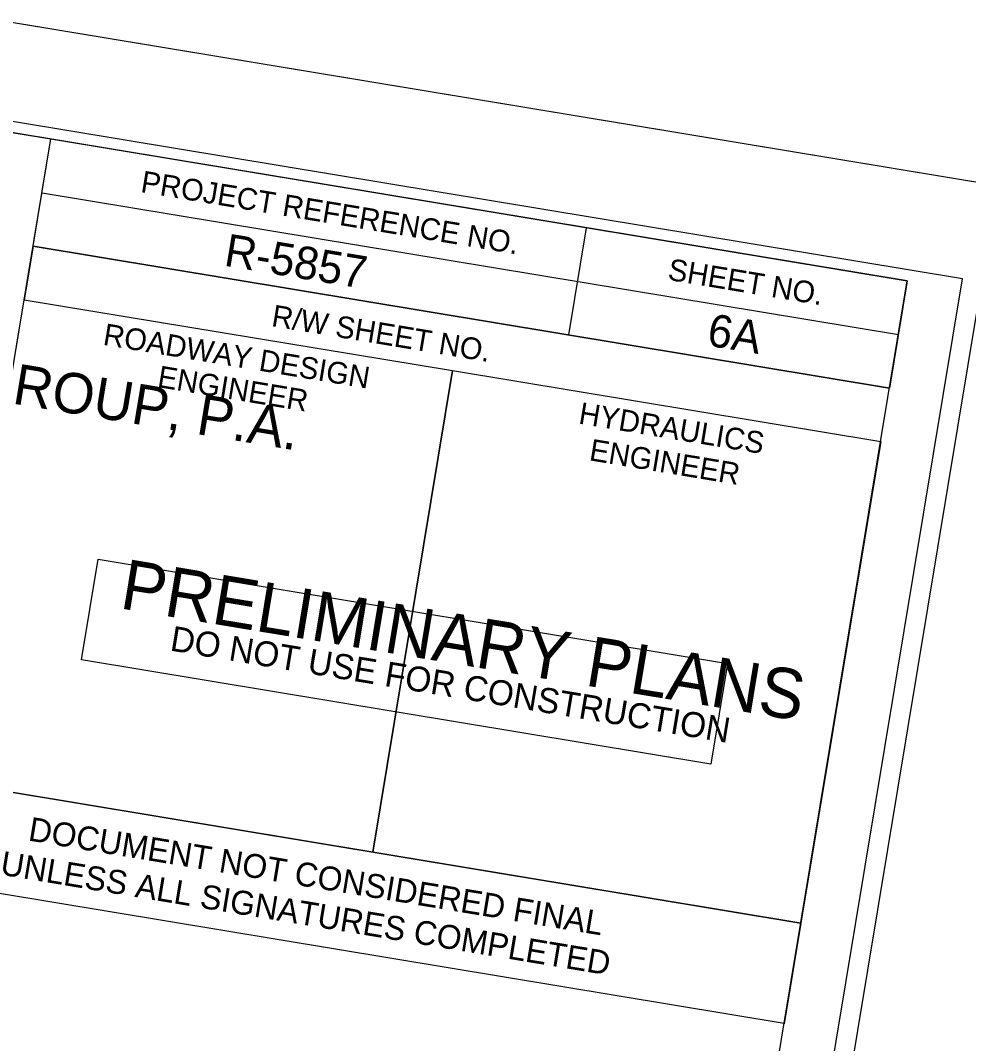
# Model space of a CAD drawing. Extents: x 2191153 to 2193185, y 85349 to 86740.
# Drawn here: x 2192768.6 to 2192987.1, y 86266.7 to 86502.5 of the extents above; entities that cross this region are included whole.
import ezdxf

# ---------------------------------------------------------------- set-up
doc = ezdxf.new("R2010")
doc.units = 0
for name, color, linetype in [('CTL Primary Horizontal CELL', 7, 'Continuous'), ('CTL Primary Horizontal Cogo Comment', 7, 'Continuous'), ('CTL Primary Horizontal Cogo Elevation', 7, 'Continuous'), ('CTL Primary Horizontal Cogo Number', 7, 'Continuous'), ('Exist Other Culture Sign', 7, 'Continuous'), ('Exist Property Iron Pin CELL', 7, 'Continuous'), ('Exist Roads EOP Other', 7, 'Continuous'), ('Exist Structure Minor Storm Sewer Manhole CELL', 7, 'Continuous')]:
    doc.layers.add(name, color=color, linetype=linetype)

msp = doc.modelspace()

# ---------------------------------------------------------------- linework, layer by layer
at = {"layer": 'CTL Primary Horizontal Cogo Comment'}
msp.add_line((2192993.8, 86464.39), (2191332.46, 86739.67), dxfattribs=at)
at = {"layer": 'CTL Primary Horizontal Cogo Elevation'}
msp.add_lwpolyline([(2192993.8, 86464.39), (2191332.46, 86739.67), (2191152.64, 85654.47), (2192813.99, 85379.19)], close=True, dxfattribs=at)
at = {"layer": 'CTL Primary Horizontal Cogo Number'}
msp.add_lwpolyline([(2192985.69, 86442.98), (2191341.61, 86715.4), (2191169.13, 85674.49), (2192813.22, 85402.07)], close=True, dxfattribs=at)
at = {"layer": 'Exist Other Culture Sign'}
for p, q in [((2192773.53, 86462.83), (2192970.89, 86430.13)), ((2192898.95, 86454.72), (2192894.86, 86430.05)), ((2192771.49, 86450.5), (2192769.45, 86438.16)), ((2192771.49, 86450.5), (2192968.85, 86417.79)), ((2192771.49, 86450.5), (2192968.85, 86417.79)), ((2192868.15, 86421.81), (2192849.77, 86310.87))]:
    msp.add_line(p, q, dxfattribs=at)
for points in [[(2192972.95, 86442.51), (2191493.12, 86687.71), (2191321.48, 85651.84), (2192801.3, 85406.63)], [(2192775.59, 86475.21), (2192972.95, 86442.51), (2192968.85, 86417.79), (2192771.49, 86450.5)], [(2192769.45, 86438.16), (2192868.15, 86421.81), (2192849.76, 86310.82), (2192751.06, 86327.18)], [(2192868.15, 86421.81), (2192966.81, 86405.46), (2192948.42, 86294.48), (2192849.76, 86310.82)]]:
    msp.add_lwpolyline(points, close=True, dxfattribs=at)
at = {"layer": 'Exist Property Iron Pin CELL'}
for p in [(2192642.99, 86497.18), (2192767.67, 86427.43)]:
    msp.add_line(p, (2192775.59, 86475.21), dxfattribs=at)
at = {"layer": 'Exist Roads EOP Other'}
msp.add_lwpolyline([(2192782.6, 86355.15), (2192786.45, 86378.33), (2192931.47, 86354.3), (2192927.63, 86331.12)], close=True, dxfattribs=at)
at = {"layer": 'Exist Structure Minor Storm Sewer Manhole CELL'}
for p, q in [((2192751.06, 86327.18), (2192948.4, 86294.48)), ((2192944.56, 86271.29), (2192747.22, 86303.99)), ((2192948.4, 86294.47), (2192944.56, 86271.28))]:
    msp.add_line(p, q, dxfattribs=at)

# ---------------------------------------------------------------- texts
at = {"layer": 'CTL Primary Horizontal CELL'}
for s, p in [('R-5857', (2192815.24, 86446.03)), ('6A', (2192926.54, 86427.64))]:
    msp.add_text(s, height=7.5, rotation=350.5917, dxfattribs=at).set_placement(p)
at = {"layer": 'Exist Other Culture Sign'}
for s, height, p in [('PROJECT REFERENCE NO.', 5.0001, (2192796.07, 86463)), ('SHEET NO.', 5, (2192917.54, 86442.77)), ('SUNGATE DESIGN GROUP, P.A.', 9.3194, (2192643.47, 86434.64)), ('R/W SHEET NO.', 5.0001, (2192826.22, 86432.1)), ('ROADWAY DESIGN', 5.0001, (2192787.39, 86427.79)), ('ENGINEER', 5, (2192799.92, 86418.06)), ('HYDRAULICS', 5, (2192897, 86409.63)), ('ENGINEER', 5, (2192899.45, 86401.17))]:
    msp.add_text(s, height=height, rotation=350.5917, dxfattribs=at).set_placement(p)
at = {"layer": 'Exist Roads EOP Other'}
for s, height, p in [('PRELIMINARY PLANS', 11.52, (2192791.17, 86367.06)), ('DO NOT USE FOR CONSTRUCTION', 5.76, (2192802.83, 86357.32))]:
    msp.add_text(s, height=height, rotation=350.5917, dxfattribs=at).set_placement(p)
at = {"layer": 'Exist Structure Minor Storm Sewer Manhole CELL'}
for s, p in [('DOCUMENT NOT CONSIDERED FINAL', (2192770.15, 86313.53)), ('UNLESS ALL SIGNATURES COMPLETED', (2192763.71, 86305.67))]:
    msp.add_text(s, height=5.5, rotation=350.5917, dxfattribs=at).set_placement(p)

doc.saveas('drawing.dxf')
